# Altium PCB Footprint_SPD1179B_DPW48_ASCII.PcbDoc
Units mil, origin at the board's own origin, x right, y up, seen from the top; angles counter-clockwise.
Board outline 6000 x 4000 mil, 2 copper layers (Top Layer, Bottom Layer); 1 components, 0 nets, 49 pads, 25 vias.
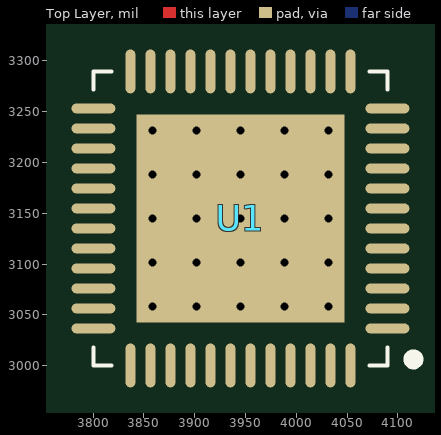
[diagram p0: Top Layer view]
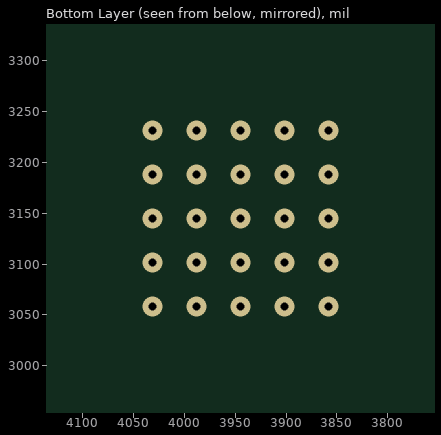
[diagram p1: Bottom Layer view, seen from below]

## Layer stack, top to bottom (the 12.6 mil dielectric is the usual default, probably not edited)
Top Solder: solder mask 0.4, Solder Resist, Dk 3.5
Top Layer: signal copper 1.4
Dielectric 1: dielectric 12.6, FR-4, Dk 4.8
Bottom Layer: signal copper 1.4
Bottom Solder: solder mask 0.4, Solder Resist, Dk 3.5

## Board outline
1000,1000 7000,1000 7000,5000 1000,5000

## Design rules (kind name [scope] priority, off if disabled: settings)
AssemblyTestPointUsage [All] p0: scope1count=1 scope1_0_kind=Board scope1_0_value=Board scope2count=1 scope2_0_kind=Board scope2_0_value=Board commentlength=0
AssemblyTestpoint [All] p0: scope1count=1 scope1_0_kind=Board scope1_0_value=Board scope2count=1 scope2_0_kind=Board scope2_0_value=Board commentlength=0
Clearance [All] p0: scope1count=1 scope1_0_kind=Board scope1_0_value=Board scope2count=1 scope2_0_kind=Board scope2_0_value=Board commentlength=0 gap=10
Clearance [All] p1: gap=10 ignorepadtopadclearanceinfootprint=FALSE except(0: Arc-Hole Track-Hole SMDPad-Hole THPad-Hole Via-Hole Fill-Hole Poly-Hole Region-Hole Text-Hole)
ComponentClearance [All] p0: scope1count=1 scope1_0_kind=Board scope1_0_value=Board scope2count=1 scope2_0_kind=Board scope2_0_value=Board commentlength=0 gap=10 collisioncheckmode=3
DiffPairsRouting [All] p0: scope1count=1 scope1_0_kind=Board scope1_0_value=Board scope2count=1 scope2_0_kind=Board scope2_0_value=Board commentlength=0
FabricationTestPointUsage [All] p0: scope1count=1 scope1_0_kind=Board scope1_0_value=Board scope2count=1 scope2_0_kind=Board scope2_0_value=Board commentlength=0 valid=0 allowmultiple=FALSE
FabricationTestpoint [All] p0: scope1count=1 scope1_0_kind=Board scope1_0_value=Board scope2count=1 scope2_0_kind=Board scope2_0_value=Board commentlength=0 side=3 testpointundercomponent=TRUE minsize=40 maxsize=100 preferedsize=60 minholesize=0 maxholesize=40 preferedholesize=32 testpointgrid=1
FanoutControl Fanout_BGA [All] p0 off: scope1count=1 scope1_0_kind=Board scope1_0_value=Board scope2count=1 scope2_0_kind=Board scope2_0_value=Board commentlength=69 // Protel DXP Scope 1 Expression Was: IsBGA   Fanout_BGA (Default Rule)
FanoutControl Fanout_LCC [All] p0 off: scope1count=1 scope1_0_kind=Board scope1_0_value=Board scope2count=1 scope2_0_kind=Board scope2_0_value=Board commentlength=69 // Protel DXP Scope 1 Expression Was: IsLCC   Fanout_LCC (Default Rule)
FanoutControl Fanout_SOIC [All] p0 off: scope1count=1 scope1_0_kind=Board scope1_0_value=Board scope2count=1 scope2_0_kind=Board scope2_0_value=Board commentlength=71 // Protel DXP Scope 1 Expression Was: IsSOIC   Fanout_SOIC (Default Rule)
FanoutControl Fanout_Small [All] p0 off: scope1count=1 scope1_0_kind=Board scope1_0_value=Board scope2count=1 scope2_0_kind=Board scope2_0_value=Board commentlength=84 // Protel DXP Scope 1 Expression Was: (CompPinCount < 5)   Fanout_Small (Default Rule)
FanoutControl Fanout_Default [All] p0: scope1count=1 scope1_0_kind=Board scope1_0_value=Board scope2count=1 scope2_0_kind=Board scope2_0_value=Board commentlength=30 // Fanout_Default (Default Rule)
Height [All] p0: scope1count=1 scope1_0_kind=Board scope1_0_value=Board scope2count=1 scope2_0_kind=Board scope2_0_value=Board commentlength=0
HoleSize [All] p0: scope1count=1 scope1_0_kind=Board scope1_0_value=Board scope2count=1 scope2_0_kind=Board scope2_0_value=Board commentlength=0 absolutevalues=TRUE maxlimit=100 minlimit=1 maxpercent=80.000 minpercent=20.000
HoleToHoleClearance [All] p0: scope1count=1 scope1_0_kind=Board scope1_0_value=Board scope2count=1 scope2_0_kind=Board scope2_0_value=Board commentlength=0
LayerPairs [All] p0: scope1count=1 scope1_0_kind=Board scope1_0_value=Board scope2count=1 scope2_0_kind=Board scope2_0_value=Board commentlength=0 enforce=TRUE
MinimumSolderMaskSliver [All] p0: scope1count=1 scope1_0_kind=Board scope1_0_value=Board scope2count=1 scope2_0_kind=Board scope2_0_value=Board commentlength=0
NetAntennae [All] p0: scope1count=1 scope1_0_kind=Board scope1_0_value=Board scope2count=1 scope2_0_kind=Board scope2_0_value=Board commentlength=0
PasteMaskExpansion [All] p0: scope1count=1 scope1_0_kind=Board scope1_0_value=Board scope2count=1 scope2_0_kind=Board scope2_0_value=Board commentlength=0 expansion=0
PlaneClearance [All] p0: scope1count=1 scope1_0_kind=Board scope1_0_value=Board scope2count=1 scope2_0_kind=Board scope2_0_value=Board commentlength=0 clearance=20
PlaneConnect [All] p0: scope1count=1 scope1_0_kind=Board scope1_0_value=Board scope2count=1 scope2_0_kind=Board scope2_0_value=Board commentlength=0 planeconnectstyle=Relief reliefexpansion=20 reliefentries=4 reliefconductorwidth=10 reliefairgap=10
PolygonConnect [All] p0: scope1count=1 scope1_0_kind=Board scope1_0_value=Board scope2count=1 scope2_0_kind=Board scope2_0_value=Board commentlength=0 connectstyle=Relief reliefconductorwidth=10 reliefentries=4 polygonreliefangle="90 Angle"
PolygonConnect [All] p1: connectstyle=Relief reliefconductorwidth=10 reliefentries=4 polygonreliefangle="90 Angle" airgapwidth=10
RoutingCorners [All] p0: scope1count=1 scope1_0_kind=Board scope1_0_value=Board scope2count=1 scope2_0_kind=Board scope2_0_value=Board commentlength=0 cornerstyle=45-Degree minsetback=100 maxsetback=100
RoutingLayers [All] p0: scope1count=1 scope1_0_kind=Board scope1_0_value=Board scope2count=1 scope2_0_kind=Board scope2_0_value=Board commentlength=0 top layer=Automatic bottom layer=Automatic
RoutingPriority [All] p0: scope1count=1 scope1_0_kind=Board scope1_0_value=Board scope2count=1 scope2_0_kind=Board scope2_0_value=Board commentlength=0
RoutingTopology [All] p0: scope1count=1 scope1_0_kind=Board scope1_0_value=Board scope2count=1 scope2_0_kind=Board scope2_0_value=Board commentlength=0 topology=Shortest
RoutingVias [All] p0: scope1count=1 scope1_0_kind=Board scope1_0_value=Board scope2count=1 scope2_0_kind=Board scope2_0_value=Board commentlength=0 holewidth=28 width=50 viastyle="Through Hole" minholewidth=28 minwidth=50 maxholewidth=28 maxwidth=50
RoutingVias [All] p1: holewidth=28 width=50 viastyle="Through Hole" minholewidth=28 minwidth=50 maxholewidth=28 maxwidth=50
ShortCircuit [All] p0: scope1count=1 scope1_0_kind=Board scope1_0_value=Board scope2count=1 scope2_0_kind=Board scope2_0_value=Board commentlength=0 allowed=FALSE
SilkToBoardRegionClearance [All] p0: scope1count=1 scope1_0_kind=Board scope1_0_value=Board scope2count=1 scope2_0_kind=Board scope2_0_value=Board commentlength=0
SilkToSilkClearance [All] p0: scope1count=1 scope1_0_kind=Board scope1_0_value=Board scope2count=1 scope2_0_kind=Board scope2_0_value=Board commentlength=0
SilkToSolderMaskClearance [All] p0 off: scope1count=1 scope1_0_kind=Board scope1_0_value=Board scope2count=1 scope2_0_kind=Board scope2_0_value=Board commentlength=44 // Protel DXP Scope 1 Expression Was: IsPad
SolderMaskExpansion [All] p0: scope1count=1 scope1_0_kind=Board scope1_0_value=Board scope2count=1 scope2_0_kind=Board scope2_0_value=Board commentlength=0 expansion=4
SolderMaskExpansion [All] p1: expansion=4 istentingtop=FALSE
UnRoutedNet [All] p0: scope1count=1 scope1_0_kind=Board scope1_0_value=Board scope2count=1 scope2_0_kind=Board scope2_0_value=Board commentlength=0
UnpouredPolygon [All] p0: scope1count=1 scope1_0_kind=Board scope1_0_value=Board scope2count=1 scope2_0_kind=Board scope2_0_value=Board commentlength=0
Width [All] p0: scope1count=1 scope1_0_kind=Board scope1_0_value=Board scope2count=1 scope2_0_kind=Board scope2_0_value=Board commentlength=0 maxlimit=10 minlimit=10 preferedwidth=10
Width [All] p1: maxlimit=10 minlimit=10 preferedwidth=10
30 further rules are at their usual default settings.

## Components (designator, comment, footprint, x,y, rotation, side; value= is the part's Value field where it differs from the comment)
U1 "" QFN48-0.5-1179-QFN50P700X700X90_HS-49M 3945,3145 r180 top

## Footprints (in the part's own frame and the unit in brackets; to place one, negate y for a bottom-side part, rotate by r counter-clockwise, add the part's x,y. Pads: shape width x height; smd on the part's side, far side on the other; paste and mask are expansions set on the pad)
QFN48-0.5-1179-QFN50P700X700X90_HS-49M [mm] "QFN, 48-Leads, Body 7.00x7.00mm, Pitch 0.50mm, Thermal Pad 5.20x5.20mm, IPC Low Density"
  oval 1.1x0.25 smd: 1(-3.675,2.75) 2(-3.675,2.25) 3(-3.675,1.75) 4(-3.675,1.25) 5(-3.675,0.75) 6(-3.675,0.25) 7(-3.675,-0.25) 8(-3.675,-0.75) 9(-3.675,-1.25) 10(-3.675,-1.75) 11(-3.675,-2.25) 12(-3.675,-2.75) 25(3.675,-2.75) 26(3.675,-2.25) 27(3.675,-1.75) 28(3.675,-1.25) 29(3.675,-0.75) 30(3.675,-0.25) 31(3.675,0.25) 32(3.675,0.75) 33(3.675,1.25) 34(3.675,1.75) 35(3.675,2.25) 36(3.675,2.75)
  oval 0.25x1.1 smd: 13(-2.75,-3.675) 14(-2.25,-3.675) 15(-1.75,-3.675) 16(-1.25,-3.675) 17(-0.75,-3.675) 18(-0.25,-3.675) 19(0.25,-3.675) 20(0.75,-3.675) 21(1.25,-3.675) 22(1.75,-3.675) 23(2.25,-3.675) 24(2.75,-3.675) 37(2.75,3.675) 38(2.25,3.675) 39(1.75,3.675) 40(1.25,3.675) 41(0.75,3.675) 42(0.25,3.675) 43(-0.25,3.675) 44(-0.75,3.675) 45(-1.25,3.675) 46(-1.75,3.675) 47(-2.25,3.675) 48(-2.75,3.675)
  rect 5.2x5.2 smd: 49(0,0)
  silkscreen extent -4.45,-3.68 3.68,3.67

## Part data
U1: library part U_SPD1179, "32-bit ARM CM4 automotives MCU with HV power management, LIN and PDRV"

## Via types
v1: diameter 19.68, hole 7.87, Top Layer to Bottom Layer, 25 vias

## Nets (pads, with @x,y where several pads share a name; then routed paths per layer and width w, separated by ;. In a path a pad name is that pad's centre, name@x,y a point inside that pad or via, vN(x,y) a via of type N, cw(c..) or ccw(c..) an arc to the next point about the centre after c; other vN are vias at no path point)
pads on no net: U1.1 U1.2 U1.3 U1.4 U1.5 U1.6 U1.7 U1.8 U1.9 U1.10 U1.11 U1.12 U1.13 U1.14 U1.15 U1.16 U1.17 U1.18 U1.19 U1.20 U1.21 U1.22 U1.23 U1.24 U1.25 U1.26 U1.27 U1.28 U1.29 U1.30 U1.31 U1.32 U1.33 U1.34 U1.35 U1.36 U1.37 U1.38 U1.39 U1.40 U1.41 U1.42 U1.43 U1.44 U1.45 U1.46 U1.47 U1.48 U1.49
copper on no net:
  other v1: 3858.39,3058.39 3901.69,3058.39 3945,3058.39 3988.31,3058.39 4031.61,3058.39 3858.39,3101.69 3901.69,3101.69 3945,3101.69 3988.31,3101.69 4031.61,3101.69 3858.39,3145 3901.69,3145 3945,3145 3988.31,3145 4031.61,3145 3858.39,3188.31 3901.69,3188.31 3945,3188.31 3988.31,3188.31 4031.61,3188.31 3858.39,3231.61 3901.69,3231.61 3945,3231.61 3988.31,3231.61 4031.61,3231.61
